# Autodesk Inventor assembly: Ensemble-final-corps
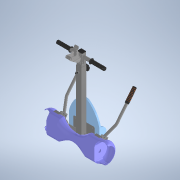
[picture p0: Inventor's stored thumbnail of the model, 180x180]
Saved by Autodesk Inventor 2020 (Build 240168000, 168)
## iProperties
Created: 2022-10
Part Number: Ensemble-final-corps
Document SubType Name: Assembly
Designer: bruno
Author: bruno
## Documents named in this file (5)
- C:\Users\bruno\Documents\1-Cours-2022-23\1SI\2. Cinématique\Hoverboard\Inventor-Hoverboard\Ensemble-final-corps.iam
- C:\Users\bruno\Documents\1-Cours-2022-23\1SI\2. Cinématique\Hoverboard\Inventor-Hoverboard\hover2.iam
- C:\Users\bruno\Documents\1-Cours-2022-23\1SI\2. Cinématique\Hoverboard\Inventor-Hoverboard\Tube-carre-2.ipt
- C:\Users\bruno\Documents\1-Cours-2022-23\1SI\2. Cinématique\Hoverboard\Inventor-Hoverboard\Hoverboard.ipt
- C:\Users\bruno\Documents\1-Cours-2022-23\1SI\2. Cinématique\Hoverboard\Inventor-Hoverboard\LKPA-VPA 101K-FI.ipt
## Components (4 placed, 4 different names)
1. hover2:1 [sub-assembly] — Placage:1, Placage:2, Placage:3, Placage:4, Placage:5, Placage:6, Affleurement:1, Affleurement:2
2. Tube-carre-2:1 — Placage:1, Placage:2
3. Hoverboard:1 — Placage:3, Placage:4, Placage:5
4. LKPA-VPA 101K-FI:1 — Placage:6, Affleurement:1, Affleurement:2
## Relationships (8: Mate 6, Flush 2)
- Placage:1 [Mate]: hover2:1 ↔ Tube-carre-2:1
- Placage:2 [Mate]: hover2:1 ↔ Tube-carre-2:1
- Placage:3 [Mate]: hover2:1 ↔ Hoverboard:1
- Placage:4 [Mate]: hover2:1 ↔ Hoverboard:1
- Placage:5 [Mate]: hover2:1 ↔ Hoverboard:1
- Placage:6 [Mate]: hover2:1 ↔ LKPA-VPA 101K-FI:1
- Affleurement:1 [Flush]: hover2:1 ↔ LKPA-VPA 101K-FI:1
- Affleurement:2 [Flush]: hover2:1 ↔ LKPA-VPA 101K-FI:1
